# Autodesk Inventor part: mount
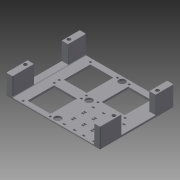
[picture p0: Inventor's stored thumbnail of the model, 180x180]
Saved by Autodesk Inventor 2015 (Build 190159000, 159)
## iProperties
Created: 2014-09
Part Number: mount
Material: Generic
Document SubType Name: Modeling
Designer: carlos
Density: 1 g/cm^3
Appearance: Default
Author: carlos
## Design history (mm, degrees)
sketch "Sketch1"
  geometry: L1 (169.258, 137.321)-(-15.742, 137.321); L2 (-15.742, 137.321)-(-15.742, -7.679); L3 (-15.742, -7.679)-(169.258, -7.679); L4 (169.258, -7.679)-(169.258, 137.321); L5 (156.258, 137.321)-(156.258, -7.679); L6 (-2.742, -7.679)-(-2.742, 137.321); C1 r 6.35 at (75.884, 2.308); C2 r 6.35 at (76.187, 128.504); C3 r 1.835 at (86.922, 132.484); C4 r 1.835 at (140.222, 132.484); C5 r 1.835 at (86.922, 71.284); C6 r 1.835 at (140.222, 71.284); C7 r 1.835 at (86.922, 61.482); C8 r 1.835 at (140.222, 61.482); C9 r 1.835 at (86.922, 0.282); C10 r 1.835 at (140.222, 0.282); C11 r 1.835 at (10.881, 61.482); C12 r 1.835 at (64.181, 61.482); C13 r 1.835 at (10.881, 0.282); C14 r 1.835 at (64.181, 0.282); C15 r 6.35 at (76.187, 66.911)
  constraints: 15 centre point, 12 end point, 4 point on line, 3 perpendicular, 2 parallel, 1 horizontal
  dimensions: "d0" = 185 distance between parallel lines of L2 L4; "d1" = 145 distance between parallel lines of L1 L3; "d14" = 13 distance between parallel lines of L4 L5; "d15" = 13 distance between parallel lines of L2 L6; "d34" = 12.7 diameter of C1; "d45" = 12.7 diameter of C2; "d67" = 3.67 diameter of C4; "d68" = 53.3 distance of C4.centre C3.centre; "d69" = 61.2 distance of C4.centre C6.centre; "d70" = 53.3 distance of C6.centre C5.centre; "d71" = 3.67 diameter of C8; "d72" = 53.3 distance of C8.centre C7.centre; "d73" = 61.2 distance of C8.centre C10.centre; "d74" = 53.3 distance of C10.centre C9.centre; "d95" = 61.2 distance of C5.centre C3.centre; "d96" = 61.2 distance of C9.centre C7.centre; "d98" = 3.67 diameter of C12; "d99" = 53.3 distance of C12.centre C11.centre; "d100" = 61.2 distance of C12.centre C14.centre; "d101" = 53.3 distance of C14.centre C13.centre; "d102" = 61.2 distance of C13.centre C11.centre; "d116" = 12.7 diameter of C15
extrude "Extrusion1" new body sketch "Sketch1" distance "d16" = 40; taper "d17" = 0 deg
sketch "Sketch2"
  geometry: 1 further point
workplane "Work Plane1"
sketch "Sketch6" dims "d61" = 180.34, "d64" = 92.08
  geometry: L1 (-181.232, 69.63)-(-101.474, 69.63); L2 (-101.474, 69.63)-(-101.474, 135.779); L3 (-178.5, 145)-(-178.5, 0) reference; L4 (6.5, 145)-(6.5, 19.766); L5 (6.5, 0)-(6.5, 145) reference; C1 r 3.205 at (-173, 118.158); C2 r 3.205 at (0.97, 118.158); C3 r 3.205 at (-173, 32.478); C4 r 3.205 at (0.97, 32.478)
  constraints: 6 end point, 4 centre point, 3 horizontal, 2 vertical, 1 perpendicular, 1 point on line
  dimensions: "d75" = 6.41 diameter of C1; "d78" = 173.97 distance of C1.centre C2.centre; "d81" = 85.68 distance of C1.centre C3.centre; "d93" = 173.97 distance of C4.centre C3.centre; "d94" = 85.68 distance of C4.centre C2.centre; "d105" = 5.5 distance from line of L3 C1.centre; "d106" = 5.53 distance from line of L4 C2.centre
hole "Hole1" sketch "Sketch6" at (-173, 118.158), (-173, 32.478), (0.97, 118.158), (0.97, 32.478) diameter "d84" = 2.35; stored, may be unused: countersink angle "d88" = 90 deg, drill point angle "d90" = 0 deg; dims "d85" = 6, "d86" = 7, "d87" = 5, "d89" = 27
extrude "Extrusion5" join sketch "Sketch1" distance "d103" = 4; taper "d104" = 0 deg
fillet "Fillet1" dims "d107" = 2
fillet "Fillet2" dims "d108" = 2
fillet "Fillet3" dims "d109" = 2
fillet "Fillet4" dims "d110" = 0.7
fillet "Fillet7" dims "d113" = 0.9
fillet "Fillet8" dims "d114" = 0.9
fillet "Fillet9" dims "d115" = 0.9
extrude "Extrusion6" cut sketch "Sketch1" stored distance "d117" = 3; taper "d118" = 0 deg
fillet "Fillet11" dims "d120" = 0.9
sketch "Sketch7"
  geometry: L1 (-24.501, 129.81)-(-24.501, 118.91); L2 (-24.501, 118.91)-(2.799, 118.91); L3 (2.799, 118.91)-(2.799, 129.81); L4 (2.799, 129.81)-(-24.501, 129.81); L5 (1.513, 117.791)-(-3.487, 117.791); L6 (-3.487, 117.791)-(-3.487, 114.791); L7 (-3.487, 114.791)-(1.513, 114.791); L8 (1.513, 114.791)-(1.513, 117.791); L9 (-18.817, 114.791)-(-18.817, 117.791); L10 (-23.817, 114.791)-(-18.817, 114.791); L11 (-23.817, 117.791)-(-23.817, 114.791); L12 (-18.817, 117.791)-(-23.817, 117.791); L13 (1.513, 134.083)-(-3.487, 134.083); L14 (-3.487, 134.083)-(-3.487, 131.083); L15 (-3.487, 131.083)-(1.513, 131.083); L16 (1.513, 131.083)-(1.513, 134.083); L17 (-18.817, 131.083)-(-18.817, 134.083); L18 (-23.817, 131.083)-(-18.817, 131.083); L19 (-23.817, 134.083)-(-23.817, 131.083); L20 (-18.817, 134.083)-(-23.817, 134.083); L21 (-18.8, 94.183)-(-18.8, 97.183); L22 (-23.8, 94.183)-(-18.8, 94.183); L23 (-23.8, 97.183)-(-23.8, 94.183); L24 (-18.8, 110.474)-(-18.8, 113.474); L25 (-23.8, 110.474)-(-18.8, 110.474); L26 (-18.8, 113.474)-(-23.8, 113.474); L27 (-23.8, 113.474)-(-23.8, 110.474); L28 (-24.484, 109.202)-(-24.484, 98.302); L29 (2.816, 109.202)-(-24.484, 109.202); L30 (-24.484, 98.302)-(2.816, 98.302); L31 (-3.47, 113.474)-(-3.47, 110.474); L32 (1.53, 113.474)-(-3.47, 113.474); L33 (1.53, 110.474)-(1.53, 113.474); L34 (-3.47, 110.474)-(1.53, 110.474); L35 (2.816, 98.302)-(2.816, 109.202); L36 (-3.47, 97.183)-(-3.47, 94.183); L37 (1.53, 97.183)-(-3.47, 97.183); L38 (1.53, 94.183)-(1.53, 97.183); L39 (-3.47, 94.183)-(1.53, 94.183); L40 (-18.8, 97.183)-(-23.8, 97.183); L41 (-18.8, 72.182)-(-18.8, 75.182); L42 (-23.8, 72.182)-(-18.8, 72.182); L43 (-23.8, 75.182)-(-23.8, 72.182); L44 (-18.8, 88.474)-(-18.8, 91.474); L45 (-23.8, 88.474)-(-18.8, 88.474); L46 (-18.8, 91.474)-(-23.8, 91.474); L47 (-23.8, 91.474)-(-23.8, 88.474); L48 (-24.484, 87.201)-(-24.484, 76.301); L49 (2.816, 87.201)-(-24.484, 87.201); L50 (-24.484, 76.301)-(2.816, 76.301); L51 (-3.47, 91.474)-(-3.47, 88.474); L52 (1.53, 91.474)-(-3.47, 91.474); L53 (1.53, 88.474)-(1.53, 91.474); L54 (-3.47, 88.474)-(1.53, 88.474); L55 (2.816, 76.301)-(2.816, 87.201); L56 (-3.47, 75.182)-(-3.47, 72.182); L57 (1.53, 75.182)-(-3.47, 75.182); L58 (1.53, 72.182)-(1.53, 75.182); L59 (-3.47, 72.182)-(1.53, 72.182); L60 (-18.8, 75.182)-(-23.8, 75.182); L61 (-57.305, 114.373)-(-57.305, 117.373); L62 (-62.305, 114.373)-(-57.305, 114.373); L63 (-62.305, 117.373)-(-62.305, 114.373); L64 (-57.305, 130.665)-(-57.305, 133.665)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; 1 further point
  constraints: 240 end point, 60 parallel, 30 perpendicular, 24 horizontal
  dimensions: "d122" = 10.9 distance between parallel lines of L2 L4; "d123" = 27.3 distance between parallel lines of L3 L1; "d137" = 3 distance between parallel lines of L5 L7; "d138" = 5 distance between parallel lines of L6 L8; "d139" = 3 distance between parallel lines of L12 L10; "d140" = 5 distance between parallel lines of L11 L9; "d141" = 3 distance between parallel lines of L13 L15; "d142" = 5 distance between parallel lines of L14 L16; "d143" = 3 distance between parallel lines of L20 L18; "d144" = 5 distance between parallel lines of L19 L17; "d145" = 10.9 distance between parallel lines of L30 L29; "d146" = 27.3 distance between parallel lines of L35 L28; "d147" = 3 distance between parallel lines of L37 L39; "d148" = 5 distance between parallel lines of L36 L38; "d149" = 3 distance between parallel lines of L40 L22; "d150" = 5 distance between parallel lines of L23 L21; "d151" = 3 distance between parallel lines of L32 L34; "d152" = 5 distance between parallel lines of L31 L33; "d153" = 3 distance between parallel lines of L26 L25; "d154" = 5 distance between parallel lines of L27 L24; "d155" = 10.9 distance between parallel lines of L50 L49; "d156" = 27.3 distance between parallel lines of L55 L48; "d157" = 3 distance between parallel lines of L57 L59; "d158" = 5 distance between parallel lines of L56 L58; "d159" = 3 distance between parallel lines of L60 L42; "d160" = 5 distance between parallel lines of L43 L41; "d161" = 3 distance between parallel lines of L52 L54; "d162" = 5 distance between parallel lines of L51 L53; "d163" = 3 distance between parallel lines of L46 L45; "d164" = 5 distance between parallel lines of L47 L44; "d165" = 10.9 distance between parallel lines of L70 L69; "d166" = 27.3 distance between parallel lines of L75 L68; "d167" = 3 distance between parallel lines of L77 L79; "d168" = 5 distance between parallel lines of L76 L78; "d169" = 3 distance between parallel lines of L80 L62; "d170" = 5 distance between parallel lines of L63 L61; "d171" = 3 distance between parallel lines of L72 L74; "d172" = 5 distance between parallel lines of L71 L73; "d173" = 3 distance between parallel lines of L66 L65; "d174" = 5 distance between parallel lines of L67 L64; "d175" = 10.9 distance between parallel lines of L90 L89; "d176" = 27.3 distance between parallel lines of L95 L88; "d177" = 3 distance between parallel lines of L97 L99; "d178" = 5 distance between parallel lines of L96 L98; "d179" = 3 distance between parallel lines of L100 L82; "d180" = 5 distance between parallel lines of L83 L81; "d181" = 3 distance between parallel lines of L92 L94; "d182" = 5 distance between parallel lines of L91 L93; "d183" = 3 distance between parallel lines of L86 L85; "d184" = 5 distance between parallel lines of L87 L84; "d185" = 10.9 distance between parallel lines of L110 L109; "d186" = 27.3 distance between parallel lines of L115 L108; "d187" = 3 distance between parallel lines of L117 L119; "d188" = 5 distance between parallel lines of L116 L118; "d189" = 3 distance between parallel lines of L120 L102; "d190" = 5 distance between parallel lines of L103 L101; "d191" = 3 distance between parallel lines of L112 L114; "d192" = 5 distance between parallel lines of L111 L113; "d193" = 3 distance between parallel lines of L106 L105; "d194" = 5 distance between parallel lines of L107 L104
extrude "Extrusion7" cut sketch "Sketch7" stored distance "d195" = 10; taper "d196" = 0 deg
extrude "Extrusion8" cut sketch "Sketch7" distance "d197" = 3.9; taper "d198" = 0 deg
fillet "Fillet12" dims "d199" = 0.3
sketch "Sketch8"
  geometry: L1 (107.103, 2.878)-(40.046, 2.878); L2 (40.046, 2.878)-(40.046, 39.236); L3 (40.046, 39.236)-(107.103, 39.236); L4 (107.103, 39.236)-(107.103, 2.878); 1 further point
  constraints: 8 end point, 2 parallel, 1 horizontal, 1 perpendicular
extrude "Extrusion9" cut sketch "Sketch8" stored distance "d200" = 3.9; taper "d201" = 0 deg
fillet "Fillet13" dims "d202" = 0.5
sketch "Sketch9"
  geometry: L1 (-135.961, 128.222)-(-90.893, 128.222); L2 (-90.893, 128.222)-(-90.893, 76.156); L3 (-90.893, 76.156)-(-135.961, 76.156); L4 (-135.961, 76.156)-(-135.961, 128.222); L5 (-135.961, 56.972)-(-90.893, 56.972); L6 (-90.893, 56.972)-(-90.893, 4.906); L7 (-90.893, 4.906)-(-135.961, 4.906); L8 (-135.961, 4.906)-(-135.961, 56.972); L9 (-60.822, 57.692)-(-15.754, 57.692); L10 (-15.754, 57.692)-(-15.754, 5.626); L11 (-15.754, 5.626)-(-60.822, 5.626); L12 (-60.822, 5.626)-(-60.822, 57.692); 1 further point
  constraints: 24 end point, 6 parallel, 3 horizontal, 3 perpendicular
extrude "Extrusion10" cut sketch "Sketch9" stored distance "d203" = 10; taper "d204" = 0 deg
body "Solid1"
